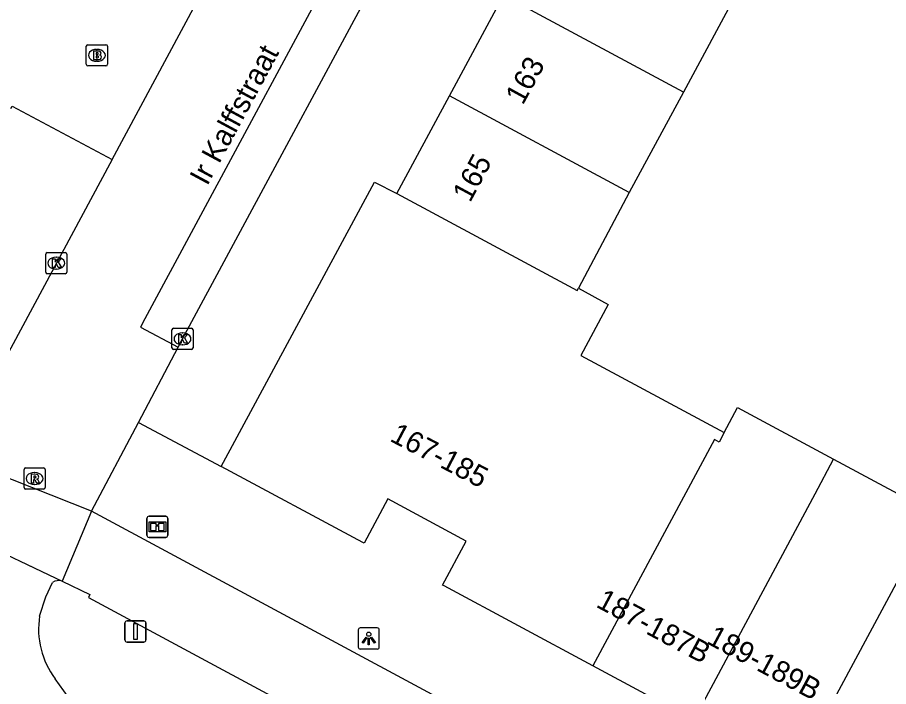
# Model space of a CAD drawing. Extents: x 159489 to 160304, y 383826 to 384530.
# Drawn here: x 159727.66 to 159768.87, y 384045.99 to 384077.66 of the extents above; entities that cross this region are included whole.
import ezdxf

# ---------------------------------------------------------------- set-up
doc = ezdxf.new("R2010")
doc.units = 0
for name, color, linetype in [('IMGEO_Brandkraan', 7, 'Continuous'), ('IMGEO_Fietspad_gesloten', 7, 'Continuous'), ('IMGEO_Informatiebord', 7, 'Continuous'), ('IMGEO_Kolk', 7, 'Continuous'), ('IMGEO_Lichtpunt', 7, 'Continuous'), ('IMGEO_Openbare_ruimte_label', 7, 'Continuous'), ('IMGEO_Pand', 7, 'Continuous'), ('IMGEO_Pand_nummerreeks', 7, 'Continuous'), ('IMGEO_Rijbaan_lokaal_gesloten', 7, 'Continuous'), ('IMGEO_Rioolput', 7, 'Continuous'), ('IMGEO_Verkeersbordpaal', 7, 'Continuous'), ('IMGEO_Voetpad_open', 7, 'Continuous')]:
    doc.layers.add(name, color=color, linetype=linetype)

msp = doc.modelspace()

# ---------------------------------------------------------------- linework, layer by layer
at = {"layer": 'IMGEO_Brandkraan'}
for p, q in [((159730.915, 384075.438), (159730.915, 384076.29)), ((159730.99, 384076.364), (159731.842, 384076.364)), ((159731.403, 384076.144), (159731.428, 384076.144)), ((159731.916, 384076.29), (159731.916, 384075.438)), ((159731.842, 384075.364), (159730.99, 384075.364)), ((159731.426, 384075.584), (159731.401, 384075.584))]:
    msp.add_line(p, q, dxfattribs=at)
for points in [[(159730.915, 384075.438), (159730.915, 384076.29)], [(159730.99, 384076.364), (159731.842, 384076.364)], [(159731.916, 384076.29), (159731.916, 384075.438)], [(159731.263, 384076.064), (159731.263, 384075.664), (159731.476, 384075.664)], [(159731.494, 384076.064), (159731.263, 384076.064)], [(159731.442, 384075.983), (159731.388, 384075.983), (159731.388, 384075.907)], [(159731.388, 384075.907), (159731.441, 384075.907)], [(159731.45, 384075.831), (159731.388, 384075.831), (159731.388, 384075.75)], [(159731.388, 384075.75), (159731.45, 384075.75)], [(159731.842, 384075.364), (159730.99, 384075.364)]]:
    msp.add_lwpolyline(points, dxfattribs=at)
for centre, radius, start, end in [((159730.992, 384076.288), 0.0765, 91.552, 178.448), ((159730.992, 384076.288), 0.0765, 91.552, 178.448), ((159731.84, 384076.288), 0.0765, 1.552, 88.448), ((159731.84, 384076.288), 0.0765, 1.552, 88.448), ((159731.443, 384075.945), 0.0379, 267.8285, 90.9355), ((159731.451, 384075.79), 0.0404, 269.8759, 90.5077), ((159731.482, 384075.915), 0.251, 268.6676, 293.5347), ((159731.498, 384075.919), 0.145, 59.4692, 91.5367), ((159731.523, 384075.966), 0.0922, 285.5137, 58.1501), ((159731.528, 384075.774), 0.105, 301.3115, 78.989), ((159730.992, 384075.44), 0.0765, 181.552, 268.448), ((159730.992, 384075.44), 0.0765, 181.552, 268.448), ((159731.84, 384075.44), 0.0765, 271.552, 358.448), ((159731.84, 384075.44), 0.0765, 271.552, 358.448)]:
    msp.add_arc(centre, radius, start, end, dxfattribs=at)
for centre, major_axis, ratio, start_param, end_param in [((159731.402, 384075.864), (-0.387, 0.002), 0.722429, 4.712389, 7.853982), ((159731.427, 384075.864), (-0.39, 0.002), 0.717154, 1.570796, 4.712389)]:
    msp.add_ellipse(centre, major_axis=major_axis, ratio=ratio, start_param=start_param, end_param=end_param, dxfattribs=at)
at = {"layer": 'IMGEO_Fietspad_gesloten'}
for points in [[(159731.166, 384054.292), (159729.77, 384050.977)], [(159797.098, 384018.803), (159731.166, 384054.292)], [(159729.77, 384050.977), (159731.079, 384050.354), (159731.013, 384050.208), (159744.588, 384042.906)]]:
    msp.add_lwpolyline(points, dxfattribs=at)
at = {"layer": 'IMGEO_Informatiebord'}
for p, q in [((159733.781, 384053.148), (159733.781, 384053.948)), ((159733.781, 384053.948), (159733.781, 384053.148)), ((159733.881, 384054.048), (159734.671, 384054.048)), ((159734.671, 384054.048), (159733.881, 384054.048)), ((159734.771, 384053.948), (159734.771, 384053.148)), ((159734.771, 384053.148), (159734.771, 384053.948)), ((159734.671, 384053.048), (159733.881, 384053.048)), ((159733.881, 384053.048), (159734.671, 384053.048))]:
    msp.add_line(p, q, dxfattribs=at)
for points in [[(159733.882, 384053.78), (159734.67, 384053.78), (159734.67, 384053.316), (159733.882, 384053.316), (159733.882, 384053.78)], [(159733.947, 384053.715), (159733.947, 384053.381), (159734.222, 384053.381), (159734.223, 384053.594), (159734.327, 384053.595), (159734.328, 384053.381), (159734.605, 384053.381), (159734.605, 384053.715), (159734.329, 384053.715), (159734.329, 384053.635), (159734.223, 384053.635), (159734.223, 384053.715), (159733.947, 384053.715)]]:
    msp.add_lwpolyline(points, dxfattribs=at)
for centre, start, end in [((159733.881, 384053.948), 90, 180), ((159733.881, 384053.948), 90, 180), ((159734.671, 384053.948), 0, 90), ((159734.671, 384053.948), 360, 90), ((159733.881, 384053.148), 180, 270), ((159733.881, 384053.148), 180, 270), ((159734.671, 384053.148), 270, 0), ((159734.671, 384053.148), 270, 0)]:
    msp.add_arc(centre, 0.1, start, end, dxfattribs=at)
at = {"layer": 'IMGEO_Kolk'}
for p, q in [((159728.994, 384065.601), (159728.994, 384066.453)), ((159729.069, 384066.527), (159729.921, 384066.527)), ((159729.482, 384066.307), (159729.507, 384066.307)), ((159729.995, 384066.453), (159729.995, 384065.601)), ((159729.921, 384065.527), (159729.069, 384065.527)), ((159729.505, 384065.747), (159729.48, 384065.747)), ((159735.039, 384062.945), (159735.891, 384062.945)), ((159734.964, 384062.019), (159734.964, 384062.871)), ((159735.452, 384062.725), (159735.477, 384062.725)), ((159735.965, 384062.871), (159735.965, 384062.019)), ((159735.475, 384062.165), (159735.45, 384062.165)), ((159735.891, 384061.945), (159735.039, 384061.945))]:
    msp.add_line(p, q, dxfattribs=at)
for points in [[(159728.994, 384065.601), (159728.994, 384066.453)], [(159729.069, 384066.527), (159729.921, 384066.527)], [(159729.315, 384066.227), (159729.438, 384066.227), (159729.438, 384066.076), (159729.568, 384066.227), (159729.732, 384066.227), (159729.586, 384066.076), (159729.739, 384065.827), (159729.587, 384065.827), (159729.502, 384065.991), (159729.438, 384065.924), (159729.438, 384065.827), (159729.315, 384065.827), (159729.315, 384066.227)], [(159729.995, 384066.453), (159729.995, 384065.601)], [(159729.921, 384065.527), (159729.069, 384065.527)], [(159735.039, 384062.945), (159735.891, 384062.945)], [(159734.964, 384062.019), (159734.964, 384062.871)], [(159735.285, 384062.645), (159735.408, 384062.645), (159735.408, 384062.494), (159735.538, 384062.645), (159735.702, 384062.645), (159735.556, 384062.494), (159735.709, 384062.245), (159735.557, 384062.245), (159735.472, 384062.409), (159735.408, 384062.342), (159735.408, 384062.245), (159735.285, 384062.245), (159735.285, 384062.645)], [(159735.965, 384062.871), (159735.965, 384062.019)], [(159735.891, 384061.945), (159735.039, 384061.945)]]:
    msp.add_lwpolyline(points, dxfattribs=at)
for centre, start, end in [((159729.071, 384066.451), 91.552, 178.448), ((159729.071, 384066.451), 91.552, 178.448), ((159729.919, 384066.451), 1.552, 88.448), ((159729.919, 384066.451), 1.552, 88.448), ((159729.071, 384065.603), 181.552, 268.448), ((159729.071, 384065.603), 181.552, 268.448), ((159729.919, 384065.603), 271.552, 358.448), ((159729.919, 384065.603), 271.552, 358.448), ((159735.041, 384062.869), 91.552, 178.448), ((159735.041, 384062.869), 91.552, 178.448), ((159735.889, 384062.869), 1.552, 88.448), ((159735.889, 384062.869), 1.552, 88.448), ((159735.041, 384062.021), 181.552, 268.448), ((159735.041, 384062.021), 181.552, 268.448), ((159735.889, 384062.021), 271.552, 358.448), ((159735.889, 384062.021), 271.552, 358.448)]:
    msp.add_arc(centre, 0.0765, start, end, dxfattribs=at)
for centre, major_axis, ratio, start_param, end_param in [((159729.481, 384066.027), (-0.387, 0.002), 0.722429, 4.712389, 7.853982), ((159729.506, 384066.027), (-0.39, 0.002), 0.717154, 1.570796, 4.712389), ((159735.451, 384062.445), (-0.387, 0.002), 0.722429, 4.712389, 7.853982), ((159735.476, 384062.445), (-0.39, 0.002), 0.717154, 1.570796, 4.712389)]:
    msp.add_ellipse(centre, major_axis=major_axis, ratio=ratio, start_param=start_param, end_param=end_param, dxfattribs=at)
at = {"layer": 'IMGEO_Lichtpunt'}
for p, q in [((159743.78, 384048.67), (159743.78, 384047.863)), ((159743.78, 384048.67), (159743.78, 384047.863)), ((159744.682, 384048.765), (159743.874, 384048.765)), ((159744.682, 384048.765), (159743.874, 384048.765)), ((159744.776, 384047.863), (159744.776, 384048.67)), ((159744.776, 384047.863), (159744.776, 384048.67)), ((159743.874, 384047.769), (159744.682, 384047.769)), ((159743.874, 384047.769), (159744.682, 384047.769))]:
    msp.add_line(p, q, dxfattribs=at)
for points in [[(159744.154, 384048.334), (159744.193, 384048.306), (159744.005, 384048.044), (159743.967, 384048.071), (159744.154, 384048.334)], [(159744.256, 384048.286), (159744.303, 384048.286), (159744.303, 384047.964), (159744.256, 384047.964), (159744.256, 384048.286)], [(159744.366, 384048.306), (159744.404, 384048.333), (159744.591, 384048.071), (159744.552, 384048.043), (159744.366, 384048.306)]]:
    msp.add_lwpolyline(points, dxfattribs=at)
msp.add_circle((159744.279, 384048.468), 0.0994, dxfattribs=at)
for centre, start, end in [((159743.874, 384048.67), 90, 180), ((159743.874, 384048.67), 90, 180), ((159744.682, 384048.67), 0, 90), ((159744.682, 384048.67), 0, 90), ((159743.874, 384047.863), 180, 270), ((159743.874, 384047.863), 180, 270), ((159744.682, 384047.863), 270, 0), ((159744.682, 384047.863), 270, 360)]:
    msp.add_arc(centre, 0.0946, start, end, dxfattribs=at)
at = {"layer": 'IMGEO_Pand'}
for points in [[(159748.091, 384073.948), (159750.647, 384078.705)], [(159759.162, 384074.125), (159750.647, 384078.705)], [(159761.719, 384078.881), (159759.162, 384074.125)], [(159759.162, 384074.125), (159756.604, 384069.369)], [(159745.606, 384069.324), (159748.091, 384073.948)], [(159756.604, 384069.369), (159748.091, 384073.948)], [(159737.293, 384056.412), (159744.543, 384069.861), (159745.606, 384069.324)], [(159745.606, 384069.324), (159754.136, 384064.736), (159754.192, 384064.841)], [(159756.604, 384069.369), (159754.192, 384064.841)], [(159754.192, 384064.841), (159755.61, 384064.079), (159754.307, 384061.657), (159761.088, 384058.01)], [(159761.088, 384058.01), (159761.728, 384059.201), (159766.267, 384056.759)], [(159761.088, 384058.01), (159760.847, 384057.561), (159760.634, 384057.677), (159754.877, 384046.966)], [(159759.654, 384044.398), (159765.389, 384055.118), (159766.267, 384056.759)], [(159766.267, 384056.759), (159771.029, 384054.198)], [(159754.877, 384046.966), (159747.838, 384050.751), (159747.763, 384050.791), (159748.885, 384052.879), (159745.177, 384054.872), (159744.059, 384052.782), (159744, 384052.814), (159737.293, 384056.412)], [(159764.388, 384041.852), (159770.147, 384052.559), (159771.029, 384054.198)], [(159759.654, 384044.398), (159754.877, 384046.966)]]:
    msp.add_lwpolyline(points, dxfattribs=at)
at = {"layer": 'IMGEO_Rijbaan_lokaal_gesloten'}
for points in [[(159732.135, 384070.941), (159785.06, 384169.44)], [(159758.71, 384105.618), (159756.933, 384106.574), (159733.684, 384063.394), (159733.476, 384062.998), (159735.26, 384062.057)], [(159732.135, 384070.941), (159724.587, 384056.893)], [(159733.379, 384058.49), (159735.26, 384062.057)], [(159731.166, 384054.292), (159733.379, 384058.49)], [(159731.166, 384054.292), (159724.587, 384056.893)], [(159722.803, 384054.291), (159729.77, 384050.977)], [(159728.705, 384049.324), (159729.003, 384050.242), (159729.317, 384050.915)], [(159731.001, 384044.339), (159730.518, 384044.924), (159730.06, 384045.499), (159729.441, 384046.354)]]:
    msp.add_lwpolyline(points, dxfattribs=at)
for centre, radius, start, end in [((159729.606, 384050.492), 0.513, 71.303, 124.2838), ((159732.611, 384048.716), 3.954, 171.1517, 216.6847)]:
    msp.add_arc(centre, radius, start, end, dxfattribs=at)
at = {"layer": 'IMGEO_Rioolput'}
for p, q in [((159728.043, 384056.335), (159728.895, 384056.335)), ((159727.968, 384055.409), (159727.968, 384056.261)), ((159728.456, 384056.115), (159728.481, 384056.115)), ((159728.969, 384056.261), (159728.969, 384055.409)), ((159728.479, 384055.555), (159728.454, 384055.555)), ((159728.895, 384055.335), (159728.043, 384055.335))]:
    msp.add_line(p, q, dxfattribs=at)
for points in [[(159728.043, 384056.335), (159728.895, 384056.335)], [(159727.968, 384055.409), (159727.968, 384056.261)], [(159728.557, 384056.033), (159728.305, 384056.035), (159728.305, 384055.635)], [(159728.483, 384055.954), (159728.429, 384055.954), (159728.429, 384055.873)], [(159728.969, 384056.261), (159728.969, 384055.409)], [(159728.305, 384055.635), (159728.429, 384055.635), (159728.429, 384055.797), (159728.44, 384055.797)], [(159728.429, 384055.873), (159728.481, 384055.873)], [(159728.487, 384055.768), (159728.558, 384055.635), (159728.698, 384055.635), (159728.633, 384055.761)], [(159728.895, 384055.335), (159728.043, 384055.335)]]:
    msp.add_lwpolyline(points, dxfattribs=at)
for centre, radius, start, end in [((159728.045, 384056.259), 0.0765, 91.552, 178.448), ((159728.045, 384056.259), 0.0765, 91.552, 178.448), ((159728.893, 384056.259), 0.0765, 1.552, 88.448), ((159728.893, 384056.259), 0.0765, 1.552, 88.448), ((159728.489, 384055.858), 0.0964, 77.0061, 93.1865), ((159728.503, 384055.915), 0.0378, 276.6634, 79.6772), ((159728.556, 384055.923), 0.109, 350.3612, 89.416), ((159728.554, 384055.923), 0.112, 277.5842, 350.9817), ((159728.439, 384055.744), 0.0533, 26.0293, 88.6989), ((159728.465, 384056.062), 0.19, 274.7715, 282.9687), ((159728.538, 384055.708), 0.108, 29.5134, 73.7905), ((159728.045, 384055.411), 0.0765, 181.552, 268.448), ((159728.045, 384055.411), 0.0765, 181.552, 268.448), ((159728.893, 384055.411), 0.0765, 271.552, 358.448), ((159728.893, 384055.411), 0.0765, 271.552, 358.448)]:
    msp.add_arc(centre, radius, start, end, dxfattribs=at)
for centre, major_axis, ratio, start_param, end_param in [((159728.455, 384055.835), (-0.387, 0.002), 0.722429, 4.712389, 7.853982), ((159728.48, 384055.835), (-0.39, 0.002), 0.717154, 1.570796, 4.712389)]:
    msp.add_ellipse(centre, major_axis=major_axis, ratio=ratio, start_param=start_param, end_param=end_param, dxfattribs=at)
at = {"layer": 'IMGEO_Verkeersbordpaal'}
for p, q in [((159732.744, 384048.199), (159732.744, 384048.999)), ((159732.744, 384048.999), (159732.744, 384048.199)), ((159732.844, 384049.099), (159733.634, 384049.099)), ((159733.634, 384049.099), (159732.844, 384049.099)), ((159733.734, 384048.999), (159733.734, 384048.199)), ((159733.734, 384048.199), (159733.734, 384048.999)), ((159733.634, 384048.099), (159732.844, 384048.099)), ((159732.844, 384048.099), (159733.634, 384048.099))]:
    msp.add_line(p, q, dxfattribs=at)
msp.add_lwpolyline([(159733.164, 384048.974), (159733.314, 384048.974), (159733.314, 384048.224), (159733.164, 384048.224), (159733.164, 384048.974)], dxfattribs=at)
for centre, start, end in [((159732.844, 384048.999), 90, 180), ((159732.844, 384048.999), 90, 180), ((159733.634, 384048.999), 0, 90), ((159733.634, 384048.999), 360, 90), ((159732.844, 384048.199), 180, 270), ((159732.844, 384048.199), 180, 270), ((159733.634, 384048.199), 270, 0), ((159733.634, 384048.199), 270, 0)]:
    msp.add_arc(centre, 0.1, start, end, dxfattribs=at)
at = {"layer": 'IMGEO_Voetpad_open'}
for points in [[(159735.26, 384062.057), (159735.465, 384062.445), (159758.71, 384105.618)], [(159727.344, 384073.348), (159727.4, 384073.454), (159732.135, 384070.941)], [(159733.379, 384058.49), (159737.293, 384056.412)]]:
    msp.add_lwpolyline(points, dxfattribs=at)

# ---------------------------------------------------------------- texts
at = {"layer": 'IMGEO_Openbare_ruimte_label'}
msp.add_text('Ir Kalffstraat', height=1, rotation=61.6915, dxfattribs=at).set_placement((159736.633, 384069.651))
at = {"layer": 'IMGEO_Pand_nummerreeks'}
for s, rotation, p in [('163', 61.3028, (159751.565, 384073.474)), ('165', 61.7913, (159749.071, 384068.863)), ('167-185', 332.3598, (159745.224, 384057.636)), ('187-187B', 331.8391, (159754.979, 384049.785)), ('189-189B', 331.6902, (159760.209, 384048.062))]:
    msp.add_text(s, height=1, rotation=rotation, dxfattribs=at).set_placement(p)

doc.saveas('drawing.dxf')
